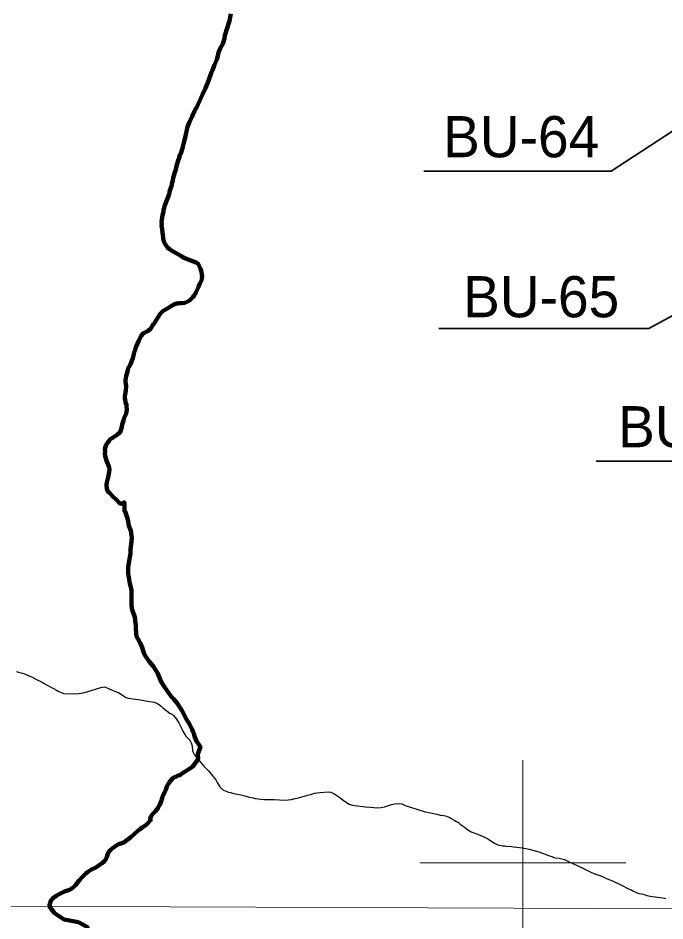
# Model space of a CAD drawing. Extents: x 553962 to 842807, y 8883888 to 9032388.
# Drawn here: x 645098 to 651378, y 8949437 to 8958207 of the extents above; entities that cross this region are included whole.
import ezdxf

# ---------------------------------------------------------------- set-up
doc = ezdxf.new("R2010")
doc.units = 0
doc.header["$LTSCALE"] = 150
for name, color, linetype, lineweight in [('1', 7, 'Continuous', 13), ('12', 7, 'Continuous', 25), ('2', 7, 'Continuous', 13), ('24', 7, 'Continuous', 25), ('40', 7, 'Continuous', 60), ('9', 7, 'Continuous', 90)]:
    doc.layers.add(name, color=color, linetype=linetype, lineweight=lineweight)

msp = doc.modelspace()

# ---------------------------------------------------------------- linework, layer by layer
at = {"layer": '1'}
msp.add_line((565315.3, 8949866.8), (791497.7, 8949052.2), dxfattribs=at)
at = {"layer": '12'}
for points in [[(645083.2, 8951861.5), (645101.9, 8951853.7), (645139.4, 8951844.3), (645159.2, 8951837.9), (645204.5, 8951819), (645240.2, 8951802.2), (645277.4, 8951781.6), (645324.7, 8951759), (645344.3, 8951747.1), (645476.8, 8951676.5), (645486.1, 8951668), (645499.5, 8951664.1), (645517.2, 8951655.3), (645535.4, 8951649), (645539.2, 8951646.5), (645633, 8951642.2), (645691.3, 8951646.6), (645709.7, 8951650.6), (645730.5, 8951653.2), (645766.4, 8951661.2), (645899.9, 8951704.4), (645939.9, 8951711), (645983.5, 8951692.1)], [(645983.5, 8951692.1), (646075.3, 8951652.5), (646111.1, 8951629), (646148, 8951608.5), (646165.6, 8951600.8), (646285, 8951585.6), (646336.2, 8951574), (646420.6, 8951561.2), (646455.4, 8951547.2), (646471.8, 8951536), (646471.8, 8951536), (646486.8, 8951523.3), (646503.8, 8951505.7), (646575.7, 8951452.5), (646594.5, 8951444.4), (646606.7, 8951433.2), (646637.1, 8951396.7), (646646.8, 8951381.7), (646658, 8951359.9), (646668.8, 8951343), (646678.2, 8951321.5), (646688, 8951304.6), (646697.6, 8951280.8), (646727.3, 8951231.4), (646758, 8951198.7), (646768, 8951185.4), (646778.9, 8951166.6), (646784.6, 8951148.8), (646787.7, 8951132.6), (646791.2, 8951093), (646800.1, 8951065.2), (646806.8, 8951054.1), (646825.7, 8951029.2), (646836.3, 8951019.3)], [(646836.3, 8951019.3), (646900.5, 8950941.1), (646947.8, 8950893.8), (646989, 8950843.2), (646999.3, 8950832.7), (647020.7, 8950801.7), (647029.2, 8950781.7), (647056, 8950740.5), (647082.1, 8950712.4), (647088.1, 8950711.7), (647092.4, 8950707.5), (647124.6, 8950692.9), (647140, 8950688.1), (647158.6, 8950685.3), (647192, 8950676), (647261.7, 8950661.8), (647311.3, 8950649.3), (647341.4, 8950639.7), (647378.7, 8950633.5), (647398.1, 8950627.8), (647482.5, 8950615.3), (647499.6, 8950617.1), (647516.6, 8950616.2), (647534.4, 8950617.1), (647567, 8950615.2), (647584.8, 8950616), (647635.2, 8950612), (647686.3, 8950610.9), (647752.8, 8950616), (647787.8, 8950625.3), (647806.4, 8950629), (647874.6, 8950648.1), (647891.6, 8950651.4), (647907.9, 8950657.4), (647927.3, 8950661.4), (647959.8, 8950672.6), (647976.9, 8950676.8), (648028, 8950685.3), (648114.8, 8950689.6), (648132.7, 8950687.8), (648148.1, 8950682.9)], [(648148.1, 8950682.9), (648164.7, 8950675), (648182.5, 8950661), (648182.5, 8950661), (648220.1, 8950634.8), (648256.1, 8950605.6), (648313.6, 8950571.5), (648330.6, 8950564.1), (648347.6, 8950561.8), (648365.5, 8950557.5), (648449.1, 8950549.1), (648469.5, 8950544.6), (648518.1, 8950542.6), (648584.7, 8950537.4), (648618.8, 8950538.4), (648656, 8950545.3), (648704, 8950560.3), (648722.7, 8950568.1), (648755.2, 8950574.3), (648790.8, 8950577.7), (648823.9, 8950574.6), (648830.2, 8950570.4), (648856.3, 8950558.2), (649040.7, 8950501.6), (649162.3, 8950475.3), (649195.7, 8950466.1), (649232.2, 8950461.1), (649246.8, 8950457.3), (649263.9, 8950450), (649281.7, 8950444.2), (649302.8, 8950433.5), (649338.4, 8950412.6), (649353.4, 8950402.1), (649372.5, 8950392.3), (649390.3, 8950378.1), (649429.6, 8950352.4), (649463.8, 8950322.8)], [(649463.8, 8950322.8), (649496, 8950302.2), (649566.4, 8950276.3), (649656.2, 8950238.2), (649697.2, 8950209.8), (649723.5, 8950193.7), (649754.2, 8950177.4), (649803.5, 8950168), (649822.1, 8950166.5), (649838.4, 8950163.6), (649890.3, 8950161.1), (649908.1, 8950157), (649941.4, 8950154.8), (649991, 8950148.7), (650043.7, 8950137.9), (650060, 8950135.7), (650094.1, 8950124.2), (650129.7, 8950116.2), (650163, 8950105.8), (650246.8, 8950073.4), (650290.2, 8950059), (650299.6, 8950053.7), (650314, 8950049.1), (650350.6, 8950046.1), (650401.7, 8950034.4), (650423.7, 8950025.5), (650495.5, 8949988.7), (650527.2, 8949975.8), (650567.9, 8949956.7), (650647.1, 8949916), (650692.9, 8949894.2), (650744.7, 8949878.8), (650786.2, 8949862.9), (650817.8, 8949847.6), (650868.1, 8949827.7), (650955.7, 8949785.1), (651029.6, 8949745.1), (651050.4, 8949738.1), (651068, 8949728), (651116.1, 8949708.1), (651168, 8949695.8), (651202.9, 8949684), (651236.2, 8949676.7), (651354.7, 8949662.8), (651372.6, 8949657.6), (651386.2, 8949655.9)]]:
    msp.add_lwpolyline(points, dxfattribs=at)
at = {"layer": '2'}
for p, q in [((650000, 8949000), (650000, 8951000)), ((649000, 8950000), (651000, 8950000))]:
    msp.add_line(p, q, dxfattribs=at)
at = {"layer": '24', "lineweight": 53}
for points in [[(647164.1, 8958249.7), (647150.1, 8958180.3), (647142.6, 8958162.4), (647125.2, 8958100), (647110, 8958058), (647106, 8958041.7), (647101.7, 8958008.2), (647087.2, 8957958.4), (647087.2, 8957958.4), (647058.3, 8957911.3), (647050.3, 8957890.4)], [(647050.3, 8957890.4), (647042.3, 8957873.9), (647037.4, 8957839), (647027, 8957805.4), (647004.7, 8957754), (646983.9, 8957699.7), (646975.5, 8957682.5), (646947.2, 8957596.2), (646930.5, 8957560.2), (646917.2, 8957527.6), (646883.4, 8957459.8), (646834.7, 8957341.3), (646821.9, 8957322.3), (646811.7, 8957303.4), (646805, 8957286.3), (646794.6, 8957269.1), (646788.3, 8957250.5), (646761.3, 8957200.6), (646741.4, 8957150.7), (646718.5, 8957047.1), (646708.9, 8957012.8), (646694.7, 8956943.6), (646676.5, 8956892.1), (646668.9, 8956874.2), (646659.3, 8956840.7), (646652.1, 8956823.5), (646643.1, 8956791.8), (646631, 8956756.6), (646628.2, 8956737.9), (646621.6, 8956719.2), (646614.4, 8956686.5), (646604.2, 8956653.8), (646599, 8956628.9), (646591.2, 8956601.5), (646589.5, 8956582.9), (646570.9, 8956533), (646569.3, 8956515.1), (646564.1, 8956498), (646526.6, 8956395.2), (646519.6, 8956378.7), (646516.8, 8956360.9), (646510.7, 8956343.7), (646508.2, 8956325.8), (646499.8, 8956291.5), (646491.5, 8956224.6), (646492.3, 8956206.6), (646491.5, 8956189.5), (646496.4, 8956156.8), (646498.8, 8956121.7), (646501.9, 8956103.8), (646505.7, 8956067), (646508.5, 8956052.4), (646513.3, 8956036.8), (646521.8, 8956017.5), (646548.8, 8955980.1), (646568.7, 8955962.5), (646602, 8955939.3), (646683.3, 8955895.3), (646701.8, 8955882.5), (646774.8, 8955850.8), (646825.4, 8955832.7), (646845.1, 8955821.4), (646854, 8955806.5), (646869, 8955770.3), (646874.6, 8955752.5), (646877, 8955735.4), (646884.3, 8955700.5), (646884.3, 8955692.1), (646882.2, 8955683.1), (646880.9, 8955666.8), (646866.5, 8955633.3), (646856.7, 8955615.4), (646850.8, 8955597.5), (646827.8, 8955543.3), (646808.2, 8955512.9), (646795.4, 8955495.8), (646766.7, 8955465.7), (646744.7, 8955453.1), (646715.6, 8955442.4), (646679.8, 8955437.7), (646662.7, 8955437.5), (646639.6, 8955435.3), (646628.3, 8955430.2), (646611.3, 8955425.7), (646593.9, 8955416.4), (646557.7, 8955391.6), (646512.4, 8955367.2), (646503.3, 8955360.9), (646478.3, 8955335.1), (646454.6, 8955300.2), (646419.3, 8955239.2), (646409, 8955231.8), (646403, 8955219.6), (646385.1, 8955192.5), (646359.3, 8955170.4), (646322, 8955149.8), (646306.6, 8955137), (646292.4, 8955120.1), (646271, 8955076.2), (646271, 8955076.2), (646238.6, 8955000.6)], [(646238.6, 8955000.6), (646233.1, 8954981.3), (646225.8, 8954962), (646222.4, 8954942.8), (646212.7, 8954904.2), (646189.9, 8954845.6), (646180.6, 8954827.1), (646167.7, 8954807), (646161.9, 8954785.9), (646154.8, 8954750), (646147.2, 8954729), (646141.1, 8954689.5), (646141.2, 8954672.9), (646146.3, 8954632.2), (646145.4, 8954591), (646134.9, 8954533.1), (646133.7, 8954513.1), (646136.6, 8954503.6), (646142, 8954472.3), (646150.6, 8954449.2), (646150.8, 8954428.7), (646153.7, 8954407.2), (646151.7, 8954379.1), (646148.4, 8954373.7), (646146, 8954363.6), (646129.2, 8954324.2), (646120.5, 8954299.3), (646109.6, 8954260), (646105.6, 8954235.9), (646100, 8954213.7), (646092.8, 8954193.2), (646087.3, 8954183.5), (646061.6, 8954162.8), (646010.4, 8954126.6), (645986.9, 8954112.3), (645983.9, 8954107.2), (645982.8, 8954099.1), (645966.6, 8954082.6), (645954.5, 8954061.9), (645945.2, 8954043), (645940.9, 8954021.6), (645941.7, 8954000.2), (645939.8, 8953978.8), (645943.5, 8953954.8), (645951.6, 8953918.8), (645959, 8953899.6), (645969.1, 8953878.7), (645981.1, 8953842.5), (645984.5, 8953823.2), (645977.2, 8953761.1), (645967.9, 8953736.2), (645958.1, 8953696.8), (645954.8, 8953674.8), (645954.9, 8953665.3), (645961, 8953634.7), (645968.4, 8953609.8), (645970, 8953607.3), (645984.2, 8953596.8), (646022.1, 8953555.9), (646049.3, 8953529.6), (646088, 8953489.3), (646092.2, 8953489.6), (646126.7, 8953501.9), (646130, 8953501.7), (646130.4, 8953416.3), (646131.4, 8953414.8), (646137.1, 8953413.1), (646163.8, 8953336.6), (646173.3, 8953276.2), (646189.2, 8953237.6), (646194.5, 8953218.3), (646195.7, 8953199.1), (646201, 8953160.5), (646200.1, 8953124.6), (646189.3, 8953044.8), (646189.1, 8953005.5), (646173, 8952915), (646166.9, 8952872.1), (646167.8, 8952832.8), (646166.9, 8952813.5), (646183.8, 8952715.8), (646190.6, 8952691.8), (646197.6, 8952651.5), (646199.9, 8952587.2), (646199, 8952500.7), (646204.9, 8952458.4), (646221.6, 8952416.4), (646234, 8952374.3), (646233.3, 8952352.9), (646239.6, 8952309.2), (646240.8, 8952267.2), (646243.7, 8952245.8), (646242.9, 8952224.4), (646246, 8952203.9), (646250.1, 8952197.4), (646252.6, 8952188.8), (646256.5, 8952186.2), (646257.9, 8952182.2), (646261.2, 8952179.2), (646263.3, 8952172.7), (646263.3, 8952172.7)], [(646263.3, 8952172.7), (646267.7, 8952169.4), (646271.2, 8952159.2), (646283.8, 8952137.9), (646294.2, 8952117.2), (646303.6, 8952093.2), (646314.2, 8952051.4), (646322.1, 8952031.6), (646333.3, 8952009.5), (646371.8, 8951955.7), (646409.8, 8951910.5), (646439.8, 8951866.6), (646450.5, 8951847.3), (646458, 8951830.6), (646472.5, 8951791.1), (646486.6, 8951759.9), (646498.1, 8951747.5), (646499.4, 8951739.7), (646505.1, 8951731.6), (646514.5, 8951713), (646583.4, 8951618.5), (646609.2, 8951590.9), (646641.2, 8951551.7), (646693.7, 8951470.3), (646714.7, 8951432.5), (646733, 8951394), (646757.5, 8951355.4), (646787.6, 8951297.6), (646794.5, 8951277.6), (646802.9, 8951258.2), (646813.5, 8951223.4), (646828.6, 8951181.9), (646867.6, 8951129.6), (646843.9, 8951061.1), (646845, 8951008.9), (646791.1, 8950934.1), (646683.1, 8950866.1), (646677.6, 8950858.9), (646671.1, 8950853.6), (646653.5, 8950848.9), (646638.2, 8950843.1), (646630.5, 8950838.5), (646616.1, 8950832.7), (646599.8, 8950823.2), (646580.2, 8950802.2), (646561.5, 8950775.5), (646560.4, 8950771.5), (646555.5, 8950768.2), (646542.3, 8950744.3), (646531.8, 8950710), (646515, 8950677.7), (646512.5, 8950667.1), (646506.4, 8950657.3), (646501.5, 8950645.9), (646497.6, 8950630.7), (646492.6, 8950619.9), (646490.9, 8950607.9), (646484.9, 8950590.5), (646469.4, 8950559.1), (646462.5, 8950548.1), (646458, 8950536.5), (646432.8, 8950502.7), (646402.4, 8950473.1), (646389.6, 8950454.9), (646380.3, 8950433.1), (646383.9, 8950415.2), (646358.3, 8950385.9), (646349.6, 8950380.1), (646346.8, 8950375.3), (646301.4, 8950345.1), (646282.4, 8950327.6), (646263.6, 8950315.1), (646191.8, 8950251), (646140.7, 8950210.9), (646124.2, 8950199.9), (646066.5, 8950178.1), (646011.5, 8950140), (645996.7, 8950128.3), (645982.6, 8950114.3), (645972, 8950100.3), (645964.6, 8950078.7), (645959.7, 8950055.9), (645950.6, 8950035.7), (645935.3, 8950018), (645917.5, 8950001), (645852.5, 8949956.4), (645811.5, 8949936.1), (645770.2, 8949910.8), (645755.5, 8949898), (645724.3, 8949866.7), (645691.2, 8949830.5), (645653.7, 8949784.5), (645634.4, 8949765.2), (645614.7, 8949747.7), (645596.6, 8949739.8), (645549.2, 8949723.6), (645488.8, 8949693.4), (645467.8, 8949680.1), (645433.2, 8949653.7), (645415.9, 8949633.6), (645398.8, 8949579.9)], [(645398.8, 8949579.9), (645451.4, 8949513.8), (645546.2, 8949449.6), (645683.8, 8949425.1), (645771.3, 8949377.1), (645790.9, 8949299.5), (645808.1, 8949229.4), (645840.2, 8949144.1), (645862.5, 8949099), (645877.2, 8949041.4), (645894.5, 8948988.8), (645929.2, 8948913.5), (645968.9, 8948848.3), (645990.2, 8948804.6)]]:
    msp.add_lwpolyline(points, dxfattribs=at)
at = {"layer": '40', "lineweight": 35}
for points in [[(652046.7, 8957498.3), (650857.4, 8956721.2), (649037.1, 8956721.2)], [(652604.9, 8955944), (651221.5, 8955191.1), (649182.7, 8955191.1)], [(653405.9, 8955846.9), (652629.2, 8953903.9), (650711.8, 8953903.9)]]:
    msp.add_lwpolyline(points, dxfattribs=at)
at = {"layer": '9'}
for points in [[(647164.1, 8958249.7), (647150.1, 8958180.3), (647142.6, 8958162.4), (647125.2, 8958100), (647110, 8958058), (647106, 8958041.7), (647101.7, 8958008.2), (647087.2, 8957958.4), (647087.2, 8957958.4), (647058.3, 8957911.3), (647050.3, 8957890.4)], [(647050.3, 8957890.4), (647042.3, 8957873.9), (647037.4, 8957839), (647027, 8957805.4), (647004.7, 8957754), (646983.9, 8957699.7), (646975.5, 8957682.5), (646947.2, 8957596.2), (646930.5, 8957560.2), (646917.2, 8957527.6), (646883.4, 8957459.8), (646834.7, 8957341.3), (646821.9, 8957322.3), (646811.7, 8957303.4), (646805, 8957286.3), (646794.6, 8957269.1), (646788.3, 8957250.5), (646761.3, 8957200.6), (646741.4, 8957150.7), (646718.5, 8957047.1), (646708.9, 8957012.8), (646694.7, 8956943.6), (646676.5, 8956892.1), (646668.9, 8956874.2), (646659.3, 8956840.7), (646652.1, 8956823.5), (646643.1, 8956791.8), (646631, 8956756.6), (646628.2, 8956737.9), (646621.6, 8956719.2), (646614.4, 8956686.5), (646604.2, 8956653.8), (646599, 8956628.9), (646591.2, 8956601.5), (646589.5, 8956582.9), (646570.9, 8956533), (646569.3, 8956515.1), (646564.1, 8956498), (646526.6, 8956395.2), (646519.6, 8956378.7), (646516.8, 8956360.9), (646510.7, 8956343.7), (646508.2, 8956325.8), (646499.8, 8956291.5), (646491.5, 8956224.6), (646492.3, 8956206.6), (646491.5, 8956189.5), (646496.4, 8956156.8), (646498.8, 8956121.7), (646501.9, 8956103.8), (646505.7, 8956067), (646508.5, 8956052.4), (646513.3, 8956036.8), (646521.8, 8956017.5), (646548.8, 8955980.1), (646568.7, 8955962.5), (646602, 8955939.3), (646683.3, 8955895.3), (646701.8, 8955882.5), (646774.8, 8955850.8), (646825.4, 8955832.7), (646845.1, 8955821.4), (646854, 8955806.5), (646869, 8955770.3), (646874.6, 8955752.5), (646877, 8955735.4), (646884.3, 8955700.5), (646884.3, 8955692.1), (646882.2, 8955683.1), (646880.9, 8955666.8), (646866.5, 8955633.3), (646856.7, 8955615.4), (646850.8, 8955597.5), (646827.8, 8955543.3), (646808.2, 8955512.9), (646795.4, 8955495.8), (646766.7, 8955465.7), (646744.7, 8955453.1), (646715.6, 8955442.4), (646679.8, 8955437.7), (646662.7, 8955437.5), (646639.6, 8955435.3), (646628.3, 8955430.2), (646611.3, 8955425.7), (646593.9, 8955416.4), (646557.7, 8955391.6), (646512.4, 8955367.2), (646503.3, 8955360.9), (646478.3, 8955335.1), (646454.6, 8955300.2), (646419.3, 8955239.2), (646409, 8955231.8), (646403, 8955219.6), (646385.1, 8955192.5), (646359.3, 8955170.4), (646322, 8955149.8), (646306.6, 8955137), (646292.4, 8955120.1), (646271, 8955076.2), (646271, 8955076.2), (646238.6, 8955000.6)], [(646238.6, 8955000.6), (646233.1, 8954981.3), (646225.8, 8954962), (646222.4, 8954942.8), (646212.7, 8954904.2), (646189.9, 8954845.6), (646180.6, 8954827.1), (646167.7, 8954807), (646161.9, 8954785.9), (646154.8, 8954750), (646147.2, 8954729), (646141.1, 8954689.5), (646141.2, 8954672.9), (646146.3, 8954632.2), (646145.4, 8954591), (646134.9, 8954533.1), (646133.7, 8954513.1), (646136.6, 8954503.6), (646142, 8954472.3), (646150.6, 8954449.2), (646150.8, 8954428.7), (646153.7, 8954407.2), (646151.7, 8954379.1), (646148.4, 8954373.7), (646146, 8954363.6), (646129.2, 8954324.2), (646120.5, 8954299.3), (646109.6, 8954260), (646105.6, 8954235.9), (646100, 8954213.7), (646092.8, 8954193.2), (646087.3, 8954183.5), (646061.6, 8954162.8), (646010.4, 8954126.6), (645986.9, 8954112.3), (645983.9, 8954107.2), (645982.8, 8954099.1), (645966.6, 8954082.6), (645954.5, 8954061.9), (645945.2, 8954043), (645940.9, 8954021.6), (645941.7, 8954000.2), (645939.8, 8953978.8), (645943.5, 8953954.8), (645951.6, 8953918.8), (645959, 8953899.6), (645969.1, 8953878.7), (645981.1, 8953842.5), (645984.5, 8953823.2), (645977.2, 8953761.1), (645967.9, 8953736.2), (645958.1, 8953696.8), (645954.8, 8953674.8), (645954.9, 8953665.3), (645961, 8953634.7), (645968.4, 8953609.8), (645970, 8953607.3), (645984.2, 8953596.8), (646022.1, 8953555.9), (646049.3, 8953529.6), (646088, 8953489.3), (646092.2, 8953489.6), (646126.7, 8953501.9), (646130, 8953501.7), (646130.4, 8953416.3), (646131.4, 8953414.8), (646137.1, 8953413.1), (646163.8, 8953336.6), (646173.3, 8953276.2), (646189.2, 8953237.6), (646194.5, 8953218.3), (646195.7, 8953199.1), (646201, 8953160.5), (646200.1, 8953124.6), (646189.3, 8953044.8), (646189.1, 8953005.5), (646173, 8952915), (646166.9, 8952872.1), (646167.8, 8952832.8), (646166.9, 8952813.5), (646183.8, 8952715.8), (646190.6, 8952691.8), (646197.6, 8952651.5), (646199.9, 8952587.2), (646199, 8952500.7), (646204.9, 8952458.4), (646221.6, 8952416.4), (646234, 8952374.3), (646233.3, 8952352.9), (646239.6, 8952309.2), (646240.8, 8952267.2), (646243.7, 8952245.8), (646242.9, 8952224.4), (646246, 8952203.9), (646250.1, 8952197.4), (646252.6, 8952188.8), (646256.5, 8952186.2), (646257.9, 8952182.2), (646261.2, 8952179.2), (646263.3, 8952172.7), (646263.3, 8952172.7)], [(646263.3, 8952172.7), (646267.7, 8952169.4), (646271.2, 8952159.2), (646283.8, 8952137.9), (646294.2, 8952117.2), (646303.6, 8952093.2), (646314.2, 8952051.4), (646322.1, 8952031.6), (646333.3, 8952009.5), (646371.8, 8951955.7), (646409.8, 8951910.5), (646439.8, 8951866.6), (646450.5, 8951847.3), (646458, 8951830.6), (646472.5, 8951791.1), (646486.6, 8951759.9), (646498.1, 8951747.5), (646499.4, 8951739.7), (646505.1, 8951731.6), (646514.5, 8951713), (646583.4, 8951618.5), (646609.2, 8951590.9), (646641.2, 8951551.7), (646693.7, 8951470.3), (646714.7, 8951432.5), (646733, 8951394), (646757.5, 8951355.4), (646787.6, 8951297.6), (646794.5, 8951277.6), (646802.9, 8951258.2), (646813.5, 8951223.4), (646828.6, 8951181.9), (646867.6, 8951129.6), (646843.9, 8951061.1), (646845, 8951008.9), (646791.1, 8950934.1), (646683.1, 8950866.1), (646677.6, 8950858.9), (646671.1, 8950853.6), (646653.5, 8950848.9), (646638.2, 8950843.1), (646630.5, 8950838.5), (646616.1, 8950832.7), (646599.8, 8950823.2), (646580.2, 8950802.2), (646561.5, 8950775.5), (646560.4, 8950771.5), (646555.5, 8950768.2), (646542.3, 8950744.3), (646531.8, 8950710), (646515, 8950677.7), (646512.5, 8950667.1), (646506.4, 8950657.3), (646501.5, 8950645.9), (646497.6, 8950630.7), (646492.6, 8950619.9), (646490.9, 8950607.9), (646484.9, 8950590.5), (646469.4, 8950559.1), (646462.5, 8950548.1), (646458, 8950536.5), (646432.8, 8950502.7), (646402.4, 8950473.1), (646389.6, 8950454.9), (646380.3, 8950433.1), (646383.9, 8950415.2), (646358.3, 8950385.9), (646349.6, 8950380.1), (646346.8, 8950375.3), (646301.4, 8950345.1), (646282.4, 8950327.6), (646263.6, 8950315.1), (646191.8, 8950251), (646140.7, 8950210.9), (646124.2, 8950199.9), (646066.5, 8950178.1), (646011.5, 8950140), (645996.7, 8950128.3), (645982.6, 8950114.3), (645972, 8950100.3), (645964.6, 8950078.7), (645959.7, 8950055.9), (645950.6, 8950035.7), (645935.3, 8950018), (645917.5, 8950001), (645852.5, 8949956.4), (645811.5, 8949936.1), (645770.2, 8949910.8), (645755.5, 8949898), (645724.3, 8949866.7), (645691.2, 8949830.5), (645653.7, 8949784.5), (645634.4, 8949765.2), (645614.7, 8949747.7), (645596.6, 8949739.8), (645549.2, 8949723.6), (645488.8, 8949693.4), (645467.8, 8949680.1), (645433.2, 8949653.7), (645415.9, 8949633.6), (645398.8, 8949579.9)], [(645398.8, 8949579.9), (645451.4, 8949513.8), (645546.2, 8949449.6), (645683.8, 8949425.1), (645771.3, 8949377.1), (645790.9, 8949299.5), (645808.1, 8949229.4), (645840.2, 8949144.1), (645862.5, 8949099), (645877.2, 8949041.4), (645894.5, 8948988.8), (645929.2, 8948913.5), (645968.9, 8948848.3), (645990.2, 8948804.6)]]:
    msp.add_lwpolyline(points, dxfattribs=at)
msp.add_spline([(637260.6, 8972975.8), (641524.5, 8971056.2), (652526.1, 8965412.7), (653164.3, 8965062.8), (670790.5, 8953770.1), (686194, 8943929.9), (696283.3, 8937647.1)], degree=3, dxfattribs=at)

# ---------------------------------------------------------------- texts
at = {"layer": '40'}
for s, p in [('BU-64', (649224.3, 8956855.1)), ('BU-65', (649418.5, 8955300.7)), ('BU-66', (650923.3, 8954037.8))]:
    msp.add_text(s, height=400, dxfattribs=at).set_placement(p)

doc.saveas('drawing.dxf')
